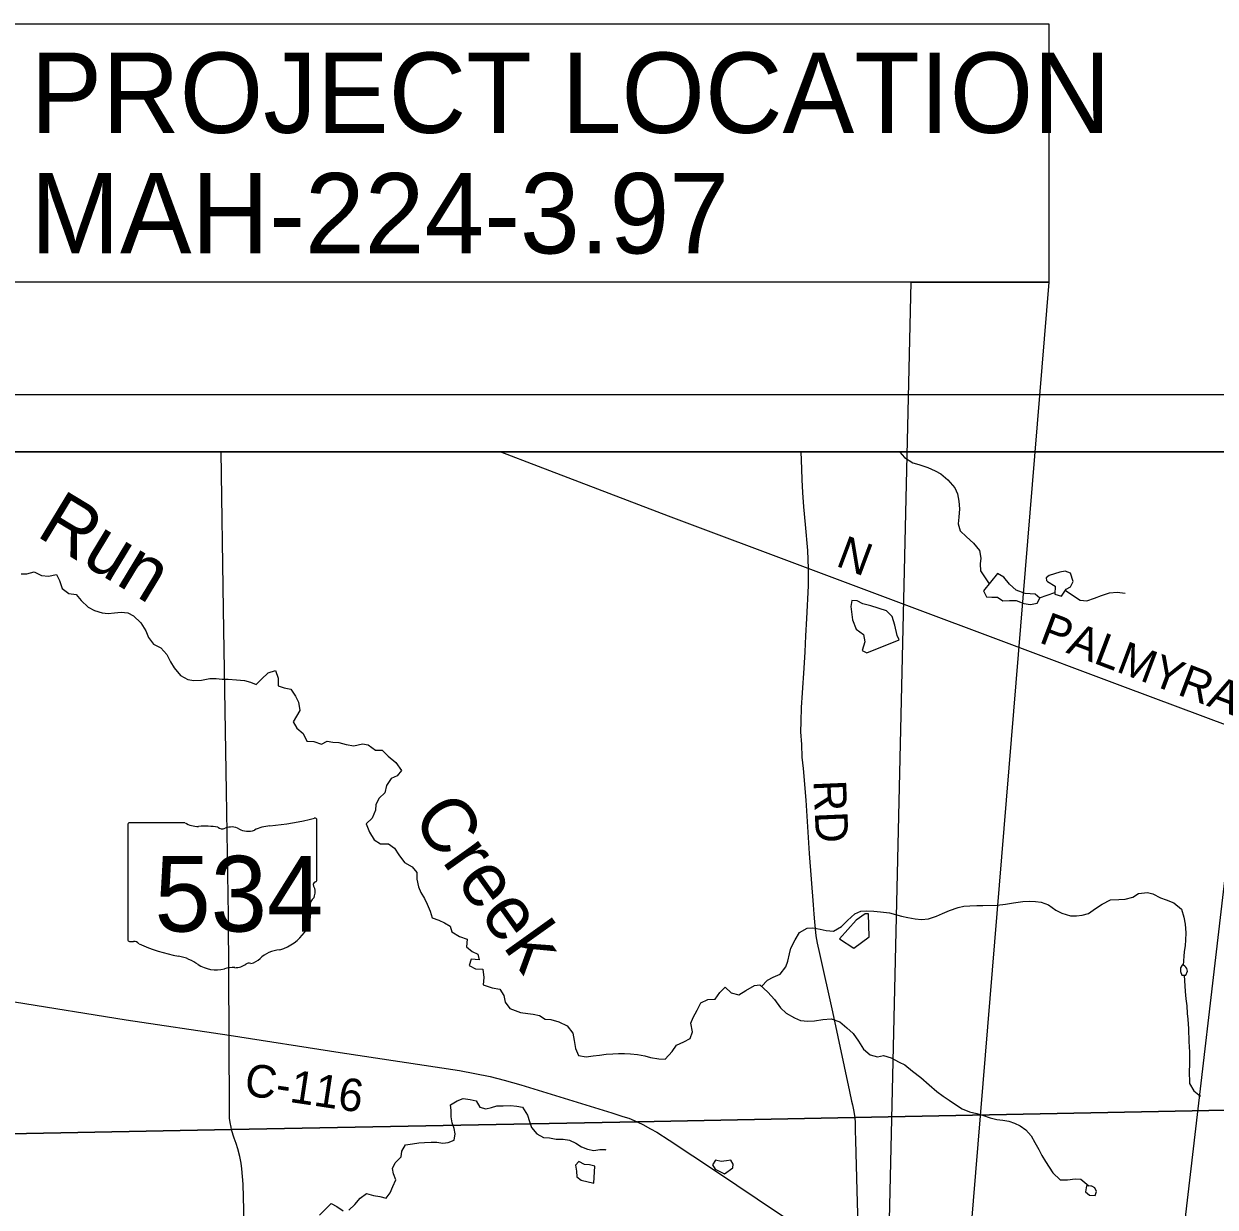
# Model space of a CAD drawing. Extents: x 0 to 34, y 0 to 22.
# Drawn here: x 4.422 to 6.498, y 18.608 to 20.67 of the extents above; entities that cross this region are included whole.
import ezdxf

# ---------------------------------------------------------------- set-up
doc = ezdxf.new("R2010")
doc.units = 0
for name, color, linetype in [('GM_X_Corporation', 7, 'Continuous'), ('GM_X_County_Road', 7, 'Continuous'), ('GM_X_County_Road_Text', 7, 'Continuous'), ('GM_X_Minor_Lake', 7, 'Continuous'), ('GM_X_Minor_River', 7, 'Continuous'), ('GM_X_Minor_River_Text', 7, 'Continuous'), ('GM_X_State_Location', 7, 'Continuous'), ('GM_X_State_Route', 7, 'Continuous'), ('GM_X_State_Shield', 7, 'Continuous'), ('SH_Data', 7, 'Continuous'), ('SH_Text', 7, 'Continuous')]:
    doc.layers.add(name, color=color, linetype=linetype)

msp = doc.modelspace()

# ---------------------------------------------------------------- linework, layer by layer
at = {"layer": 'GM_X_Corporation'}
msp.add_lwpolyline([(6.9951, 19.9239), (3.4438, 19.9239), (3.4438, 18.7173), (4.784, 18.7437), (5.4919, 18.7569), (5.8701, 18.7643), (7.0169, 18.7868), (7.0072, 19.2641), (7.0062, 19.3415), (7.0002, 19.6505)], close=True, dxfattribs=at)
msp.add_lwpolyline([(7.0169, 18.7868), (5.8701, 18.7643), (5.4919, 18.7569), (4.784, 18.7437), (3.4438, 18.7173), (3.4438, 13.5923), (3.5133, 13.5939), (4.9278, 13.619), (5.5741, 13.6306), (5.8662, 13.6357), (7.1049, 13.6572)], dxfattribs=at)
at = {"layer": 'GM_X_County_Road'}
for points in [[(5.789, 19.7211), (5.5459, 19.8123), (5.3192, 19.8985), (5.2523, 19.9239)], [(5.7762, 19.9239), (5.7772, 19.8945), (5.7782, 19.8753), (5.7791, 19.853), (5.7812, 19.8281), (5.7836, 19.7975), (5.7877, 19.7521), (5.789, 19.7211)], [(5.789, 19.7211), (5.789, 19.6905), (5.786, 19.6336), (5.7845, 19.6034), (5.7831, 19.5755), (5.7814, 19.547), (5.7785, 19.5041), (5.777, 19.4788), (5.7761, 19.4541), (5.7758, 19.4361), (5.7772, 19.4141), (5.7783, 19.3924), (5.7801, 19.3726), (5.7848, 19.3175), (5.7909, 19.2244), (5.7976, 19.1352), (5.7988, 19.1186), (5.8002, 19.1052), (5.8015, 19.0929), (5.8026, 19.0812), (5.8049, 19.068), (5.8086, 19.0502), (5.8313, 18.9487), (5.8613, 18.8095), (5.8648, 18.7931), (5.8663, 18.7864), (5.8679, 18.778), (5.8692, 18.7713), (5.8703, 18.7637)], [(7.0074, 19.2636), (6.8614, 19.3185), (6.6831, 19.3857), (6.5257, 19.4449), (6.3375, 19.5155), (6.13, 19.5931), (5.961, 19.6562), (5.789, 19.7211)], [(4.0404, 18.9967), (4.1797, 18.9979), (4.1902, 18.9977), (4.1981, 18.9975), (4.2061, 18.9971), (4.2133, 18.9962), (4.2223, 18.9949), (4.25, 18.9904), (4.4062, 18.9661), (4.6004, 18.9348), (4.7799, 18.9077)], [(4.7799, 18.9077), (4.9734, 18.8779), (5.1813, 18.8462), (5.2084, 18.8412), (5.235, 18.8357), (5.2595, 18.8297), (5.2884, 18.8214), (5.3262, 18.8096), (5.447, 18.7723), (5.4624, 18.7676)], [(5.4624, 18.7676), (5.4663, 18.7664), (5.4765, 18.763), (5.4856, 18.7592), (5.4921, 18.7563), (5.5009, 18.7521), (5.5145, 18.7449), (5.5255, 18.7387), (5.547, 18.7252), (5.6295, 18.6702), (5.7, 18.6229), (5.7532, 18.5874), (5.7843, 18.566), (5.818, 18.5413), (5.8782, 18.4947)], [(5.8703, 18.7637), (5.8708, 18.7549), (5.8712, 18.7416), (5.8717, 18.7242), (5.8739, 18.6374), (5.8782, 18.4947)]]:
    msp.add_lwpolyline(points, dxfattribs=at)
at = {"layer": 'GM_X_Minor_Lake'}
for points in [[(6.0947, 19.6819), (6.0999, 19.6714), (6.1094, 19.6712), (6.1193, 19.6707), (6.1286, 19.6648), (6.14, 19.6651), (6.1518, 19.665), (6.1652, 19.66), (6.1763, 19.6583), (6.188, 19.6605), (6.1928, 19.669), (6.1846, 19.676), (6.1671, 19.6775), (6.1514, 19.6832), (6.1401, 19.6936), (6.1303, 19.7055), (6.1191, 19.7121)], [(6.1191, 19.7121), (6.0947, 19.6819)], [(6.2279, 19.7146), (6.2093, 19.7086), (6.2038, 19.7049), (6.2044, 19.7001), (6.2062, 19.6982)], [(6.2062, 19.6982), (6.2193, 19.6901), (6.2189, 19.676), (6.2304, 19.6725), (6.2388, 19.6849), (6.246, 19.6892), (6.2511, 19.6985), (6.2465, 19.7128), (6.237, 19.716), (6.2279, 19.7146)], [(5.9476, 19.5967), (5.944, 19.6042), (5.9402, 19.622), (5.9353, 19.6375), (5.9255, 19.6471), (5.8983, 19.656), (5.8845, 19.6595), (5.8742, 19.6646), (5.865, 19.6651), (5.8634, 19.6544), (5.8666, 19.6313), (5.8726, 19.6151), (5.8854, 19.6059), (5.888, 19.593), (5.8834, 19.5781), (5.8911, 19.5737)], [(5.8911, 19.5737), (5.9476, 19.5967)], [(5.8952, 19.0791), (5.8943, 19.1194), (5.8886, 19.1193), (5.8728, 19.1085), (5.8439, 19.0754), (5.8685, 19.0593)], [(5.8685, 19.0593), (5.8952, 19.0791)], [(6.4406, 19.0299), (6.4377, 19.0253), (6.4378, 19.0185), (6.4402, 19.0124), (6.4475, 19.0126), (6.45, 19.0195), (6.4491, 19.0241), (6.4471, 19.0263)], [(6.4471, 19.0263), (6.4457, 19.0282), (6.443, 19.0297), (6.4414, 19.0302), (6.4406, 19.0299)], [(5.4173, 18.6796), (5.4078, 18.6818), (5.3994, 18.6828), (5.3894, 18.6876), (5.3838, 18.6815), (5.3851, 18.6709), (5.386, 18.661), (5.3937, 18.655), (5.4158, 18.6499)], [(5.6577, 18.6769), (5.6583, 18.6834), (5.6545, 18.6898), (5.6469, 18.6889), (5.6377, 18.688), (5.6278, 18.6898), (5.6226, 18.6818), (5.6273, 18.6746), (5.6434, 18.6664)], [(5.4158, 18.6499), (5.4173, 18.6796)], [(5.6434, 18.6664), (5.6577, 18.6769)], [(6.2743, 18.6455), (6.2723, 18.6352), (6.2796, 18.6289), (6.2895, 18.6288), (6.2917, 18.6353), (6.2888, 18.6417), (6.2834, 18.6446), (6.2815, 18.6449)], [(6.2815, 18.6449), (6.2743, 18.6455)]]:
    msp.add_lwpolyline(points, dxfattribs=at)
at = {"layer": 'GM_X_Minor_River'}
for points in [[(5.9487, 19.9239), (5.9487, 19.9237), (5.9569, 19.914), (5.9712, 19.9052), (5.9819, 19.9021), (5.9976, 19.8971), (6.0103, 19.8913), (6.0204, 19.8858), (6.0324, 19.8751), (6.0445, 19.8613), (6.0493, 19.8508), (6.0519, 19.8379), (6.0526, 19.825), (6.0518, 19.8105), (6.0505, 19.7987), (6.0539, 19.7866), (6.0648, 19.7759), (6.0772, 19.7651), (6.0874, 19.7524), (6.09, 19.7388), (6.0887, 19.7293), (6.0894, 19.7167), (6.1048, 19.6943)], [(4.4177, 19.7118), (4.4276, 19.7117), (4.4405, 19.715), (4.4528, 19.7085), (4.465, 19.7076), (4.4794, 19.7106), (4.4842, 19.7001), (4.4891, 19.6861), (4.5007, 19.6773), (4.5133, 19.6753), (4.5219, 19.6652), (4.5344, 19.6533), (4.5455, 19.6475), (4.5586, 19.6436), (4.5692, 19.6424), (4.5802, 19.6434), (4.5916, 19.6448), (4.6034, 19.6436), (4.6135, 19.6385), (4.6263, 19.6262), (4.6346, 19.612), (4.6394, 19.6007), (4.6485, 19.5891), (4.6612, 19.5829), (4.6713, 19.571), (4.6777, 19.5582), (4.684, 19.5477), (4.6954, 19.5347), (4.7081, 19.5274), (4.7184, 19.5257), (4.7321, 19.5264), (4.7465, 19.529), (4.7575, 19.5293), (4.7678, 19.528), (4.7781, 19.5283), (4.7926, 19.5267), (4.8067, 19.5255), (4.8174, 19.5231), (4.827, 19.5188), (4.8367, 19.5281), (4.8482, 19.539), (4.8607, 19.5431), (4.8655, 19.5296), (4.8655, 19.5162), (4.8762, 19.5127), (4.8877, 19.5107), (4.8956, 19.4983), (4.9007, 19.4878), (4.9034, 19.4734), (4.8975, 19.4638), (4.8917, 19.4537), (4.898, 19.4429), (4.9089, 19.4336), (4.9153, 19.4201), (4.9278, 19.4192), (4.9409, 19.415), (4.9506, 19.4202), (4.9606, 19.4181), (4.9712, 19.4176), (4.9842, 19.4145), (4.9972, 19.4121), (5.0124, 19.4155), (5.0223, 19.4138), (5.0351, 19.4043), (5.0469, 19.4045), (5.0574, 19.3938), (5.0706, 19.3827), (5.0804, 19.3692), (5.0726, 19.3595), (5.0625, 19.3551), (5.054, 19.3431), (5.0513, 19.3301), (5.0416, 19.3208), (5.0358, 19.3096), (5.0352, 19.2997), (5.0291, 19.2859), (5.0191, 19.2758), (5.0244, 19.2614), (5.033, 19.2483), (5.0438, 19.2414), (5.0575, 19.2413), (5.068, 19.2336), (5.0759, 19.222), (5.0857, 19.2089), (5.0992, 19.2012), (5.107, 19.1911), (5.1069, 19.1794), (5.1099, 19.1665), (5.1143, 19.1567), (5.1202, 19.1462), (5.1254, 19.1361), (5.1303, 19.1236)], [(6.2373, 19.6826), (6.2629, 19.6657), (6.2747, 19.6648), (6.2883, 19.6693), (6.3003, 19.6741), (6.3143, 19.6786), (6.3276, 19.6797), (6.3417, 19.6778)], [(6.1922, 19.6695), (6.219, 19.6789)], [(5.708, 18.9926), (5.7181, 19.0036), (5.7279, 19.0087), (5.7403, 19.0143), (5.7499, 19.0267), (5.7535, 19.0367), (5.7566, 19.0497), (5.759, 19.0596), (5.7667, 19.0739), (5.774, 19.087), (5.7871, 19.0945), (5.797, 19.0947), (5.81, 19.0924), (5.8207, 19.0904), (5.8333, 19.0891), (5.8472, 19.0971), (5.8579, 19.1076), (5.8702, 19.1193), (5.8808, 19.1241), (5.8906, 19.1243), (5.9036, 19.1239), (5.9154, 19.1226), (5.9307, 19.1207), (5.9414, 19.1179), (5.9517, 19.1151), (5.9628, 19.1127), (5.9754, 19.1107), (5.9868, 19.1095), (5.9986, 19.1105), (6.0129, 19.1154), (6.0231, 19.1198), (6.0355, 19.125), (6.0503, 19.1303), (6.0605, 19.1325), (6.0707, 19.1331), (6.0829, 19.1337), (6.0932, 19.1336), (6.1186, 19.1342), (6.1327, 19.136), (6.1471, 19.1383), (6.163, 19.1406), (6.1748, 19.1412), (6.1854, 19.1407), (6.1953, 19.1394), (6.208, 19.1348), (6.2208, 19.1259), (6.2312, 19.1205), (6.2461, 19.1159), (6.2568, 19.1158), (6.2666, 19.1171), (6.2776, 19.1197), (6.2896, 19.1283), (6.3012, 19.1358), (6.3158, 19.1434), (6.3306, 19.1441), (6.3413, 19.1447), (6.3549, 19.1481), (6.365, 19.1544), (6.3802, 19.1566), (6.3898, 19.1538), (6.4028, 19.1473), (6.4132, 19.1437), (6.4263, 19.1383), (6.4394, 19.1272), (6.444, 19.1133), (6.4461, 19.1015), (6.4473, 19.0864), (6.4464, 19.0734), (6.4459, 19.0639), (6.4446, 19.0532), (6.4424, 19.0299)], [(5.1303, 19.1236), (5.1336, 19.1123), (5.1455, 19.1084), (5.1551, 19.1033), (5.1655, 19.0975), (5.1684, 19.0876), (5.1815, 19.0796), (5.1946, 19.075), (5.1934, 19.0616), (5.2038, 19.0539), (5.2134, 19.0492), (5.216, 19.0393), (5.2018, 19.0405), (5.1983, 19.0294), (5.2091, 19.0232), (5.222, 19.0228), (5.2239, 19.0084), (5.2227, 18.9958), (5.2384, 18.9901), (5.2518, 18.9881), (5.2585, 18.9768), (5.2611, 18.9651), (5.2693, 18.9543), (5.2877, 18.9475), (5.3003, 18.9455), (5.3099, 18.9442), (5.3209, 18.9422), (5.3306, 18.936), (5.3405, 18.935), (5.3543, 18.9308), (5.3689, 18.9243), (5.3787, 18.9116), (5.3813, 18.8984), (5.3839, 18.8847), (5.3888, 18.8723), (5.4025, 18.8703), (5.4146, 18.8718), (5.4253, 18.8732), (5.437, 18.875), (5.4488, 18.8756), (5.4587, 18.8762), (5.4689, 18.8761), (5.4796, 18.8752), (5.4914, 18.8743), (5.5044, 18.872), (5.5144, 18.8688), (5.5289, 18.8665), (5.5399, 18.8663), (5.5518, 18.8792), (5.5595, 18.8907), (5.5727, 18.8964), (5.5832, 18.9019), (5.5875, 18.9138), (5.5848, 18.929), (5.5884, 18.9386), (5.5957, 18.9517), (5.6019, 18.9643), (5.6143, 18.97), (5.6272, 18.9703), (5.6349, 18.9822), (5.6446, 18.9916), (5.6551, 18.9816), (5.6685, 18.9781), (5.6805, 18.9856), (5.6955, 18.9943), (5.705, 18.9953), (5.719, 18.9827), (5.7307, 18.97), (5.7409, 18.9554), (5.751, 18.9462), (5.7653, 18.9378), (5.7757, 18.9334), (5.7886, 18.9322), (5.8004, 18.9329), (5.8144, 18.9351), (5.8293, 18.9362), (5.8442, 18.9312), (5.8563, 18.9205), (5.8675, 18.9109), (5.8766, 18.8974), (5.8853, 18.8835), (5.8973, 18.8735), (5.9099, 18.8704), (5.9205, 18.8726), (5.9339, 18.8683), (5.9478, 18.861), (5.9574, 18.8559), (5.971, 18.8449), (5.9853, 18.8342), (5.9997, 18.8212), (6.0133, 18.8097), (6.0241, 18.8016), (6.0349, 18.7946), (6.0477, 18.7858), (6.0577, 18.7796), (6.0704, 18.7742), (6.083, 18.7711), (6.093, 18.7686), (6.1064, 18.764), (6.1179, 18.7612), (6.1286, 18.76)], [(6.4442, 19.0125), (6.4459, 18.9837), (6.4473, 18.9712), (6.4487, 18.959), (6.4498, 18.9454), (6.4508, 18.9355), (6.452, 18.9188), (6.4525, 18.8968), (6.4537, 18.8782), (6.4539, 18.8687), (6.4534, 18.8557), (6.4529, 18.8455), (6.4534, 18.8234), (6.461, 18.8111), (6.473, 18.8014)], [(4.9889, 18.603), (4.999, 18.6126), (5.0085, 18.624), (5.0194, 18.6321), (5.0316, 18.6288), (5.0427, 18.627), (5.0537, 18.6237), (5.0605, 18.6332), (5.0653, 18.6443), (5.0705, 18.6561), (5.0666, 18.6663), (5.0647, 18.6758), (5.0695, 18.6857), (5.0797, 18.6961), (5.0811, 18.7056), (5.0875, 18.7167), (5.0996, 18.7187), (5.1107, 18.7203), (5.1205, 18.7207), (5.132, 18.7212), (5.1418, 18.7213), (5.1525, 18.7195), (5.162, 18.7211), (5.1719, 18.725), (5.174, 18.736), (5.1721, 18.7455), (5.1689, 18.755), (5.1669, 18.7656), (5.1668, 18.7766), (5.1656, 18.7865), (5.1777, 18.7934), (5.1879, 18.7977), (5.2001, 18.7955), (5.2104, 18.7933)], [(5.2104, 18.7933), (5.217, 18.7827), (5.2273, 18.7798), (5.2371, 18.7818), (5.2466, 18.7845), (5.2577, 18.785), (5.2702, 18.7851), (5.2812, 18.784), (5.2912, 18.7822), (5.3, 18.7686), (5.3035, 18.7576), (5.3071, 18.747), (5.3163, 18.736), (5.3278, 18.7297), (5.3384, 18.729), (5.3502, 18.7264), (5.3624, 18.7269), (5.3731, 18.7251), (5.3841, 18.7195), (5.3941, 18.7135), (5.4044, 18.7094), (5.4158, 18.7068), (5.4261, 18.7088), (5.4356, 18.7085), (5.4364, 18.7081)], [(6.1286, 18.76), (6.1385, 18.7583), (6.1485, 18.7547), (6.1585, 18.75), (6.1682, 18.743), (6.1775, 18.7326), (6.1839, 18.7206), (6.191, 18.7086), (6.1962, 18.6984), (6.2025, 18.6879), (6.2089, 18.6778), (6.2152, 18.6681), (6.2284, 18.6558), (6.241, 18.6558), (6.2546, 18.6576), (6.2641, 18.6567), (6.2781, 18.6452)], [(4.9376, 18.5942), (4.9576, 18.6145), (4.9675, 18.6093), (4.9786, 18.6018)]]:
    msp.add_lwpolyline(points, dxfattribs=at)
at = {"layer": 'GM_X_State_Route'}
for points in [[(4.7799, 18.9077), (4.7787, 19.1163), (4.7752, 19.3323), (4.7705, 19.6501), (4.766, 19.9239)], [(4.807, 18.5594), (4.8043, 18.648), (4.8036, 18.6616), (4.8023, 18.6749), (4.8009, 18.6849), (4.7986, 18.6964), (4.795, 18.7098), (4.7921, 18.7193), (4.7888, 18.7286), (4.7842, 18.7431), (4.7834, 18.7478), (4.7819, 18.7556), (4.7809, 18.7632), (4.7804, 18.7691), (4.7799, 18.9077)]]:
    msp.add_lwpolyline(points, dxfattribs=at)
at = {"layer": 'GM_X_State_Shield'}
for p, q in [((4.6033, 19.2744), (4.6033, 19.0743)), ((4.7031, 19.2779), (4.6066, 19.2779)), ((4.9329, 19.1782), (4.9329, 19.2828)), ((4.9329, 19.1782), (4.9329, 19.1782))]:
    msp.add_line(p, q, dxfattribs=at)
for centre, major_axis, start_param, end_param in [((4.6071, 19.2749), (0.00382, 0), 1.712693, 3.28349), ((4.7261, 19.3011), (0.037, 0), 4.042523, 4.731795), ((4.7384, 19.1655), (0.133, 0), 1.404758, 1.657858), ((4.7685, 19.2759), (0.0107, 0), 3.836095, 5.185415), ((4.7842, 19.2528), (0.0222, 0), 0.950623, 2.079405), ((4.8129, 19.2845), (0.0267, 0), 4.081561, 5.145723), ((4.8601, 19.2168), (0.0703, 0), 1.699011, 2.107814), ((4.8155, 19.5507), (0.3495, 0), 4.814394, 5.042369), ((4.9293, 19.2833), (0.00367, 0), 6.141152, 7.989035), ((4.9321, 19.1705), (0.00568, 0), 1.883978, 3.671073), ((4.8959, 19.1572), (0.0341, 0), 5.934695, 6.695948), ((4.929, 19.1778), (0.00393, 0), 5.05454, 6.418171), ((4.9461, 19.1343), (0.0248, 0), 2.387724, 3.262537), ((4.8351, 19.121), (0.0874, 0), 5.101752, 6.440018), ((4.6071, 19.0739), (0.00385, 0), 3.00124, 4.508301), ((4.6077, 19.0944), (0.0294, 0), 4.665946, 4.897461), ((4.6137, 19.0628), (0.0106, 0), 0.519207, 1.627899), ((4.7476, 19.2426), (0.2524, 0), 4.195997, 4.488961), ((4.6723, 18.9844), (0.079, 0), 0.823519, 1.323587), ((4.8113, 19.0549), (0.0282, 0), 4.937069, 5.64225), ((4.872, 19.0181), (0.0479, 0), 1.647645, 2.488434), ((4.7577, 19.0618), (0.0501, 0), 4.026481, 4.996735), ((4.7867, 18.9926), (0.0412, 0), 1.495662, 1.94098), ((4.7903, 19.0468), (0.0267, 0), 4.691044, 5.507374), ((4.8145, 19.0274), (0.00752, 0), 1.147584, 2.315152)]:
    msp.add_ellipse(centre, major_axis=major_axis, ratio=0.8, start_param=start_param, end_param=end_param, dxfattribs=at)
at = {"layer": 'SH_Data'}
for p, q in [((3.3438, 20.0239), (10.3438, 20.0239)), ((3.4438, 19.9239), (10.2438, 19.9239))]:
    msp.add_line(p, q, dxfattribs=at)
at = {"layer": 'SH_Text'}
msp.add_lwpolyline([(4.3838, 20.6698), (6.2084, 20.6698), (6.2084, 20.2198), (4.3838, 20.2198)], close=True, dxfattribs=at)
for points in [[(6.2084, 20.2198), (5.875, 16.1727), (5.9684, 20.2198), (6.2084, 20.2198)], [(6.6356, 20.2119), (6.1643, 16.1776), (6.8636, 20.2119), (6.6356, 20.2119)]]:
    msp.add_lwpolyline(points, dxfattribs=at)

# ---------------------------------------------------------------- texts
at = {"layer": 'GM_X_County_Road_Text'}
for s, height, rotation, p in [('N', 0.0568, 339.444, (5.8353, 19.7261)), ('PALMYRA', 0.05682, 339.3475, (6.1895, 19.5927)), ('RD', 0.05682, 272.4668, (5.7982, 19.3513)), ('C-116', 0.05682, 351.4425, (4.8045, 18.8036))]:
    msp.add_text(s, height=height, rotation=rotation, dxfattribs=at).set_placement(p)
at = {"layer": 'GM_X_Minor_River_Text'}
for s, rotation, p in [('Run', 328.765, (4.4418, 19.7787)), ('Creek', 305.5513, (5.0967, 19.2853))]:
    msp.add_text(s, height=0.09473, rotation=rotation, dxfattribs=at).set_placement(p)
at = {"layer": 'GM_X_State_Location'}
msp.add_text('534', height=0.000189, rotation=0, dxfattribs=at).set_placement((4.6976, 19.1473))
for s in ['s', 'r']:
    msp.add_text(s, height=0.000189, dxfattribs=at).set_placement((4.7644, 19.1611))
at = {"layer": 'GM_X_State_Shield'}
msp.add_text('534', height=0.13184, dxfattribs=at).set_placement((4.6499, 19.0884))
at = {"layer": 'SH_Text'}
for s, p in [('PROJECT LOCATION', (4.4338, 20.4798)), ('MAH-224-3.97', (4.4338, 20.2698))]:
    msp.add_text(s, height=0.14, dxfattribs=at).set_placement(p)

doc.saveas('drawing.dxf')
